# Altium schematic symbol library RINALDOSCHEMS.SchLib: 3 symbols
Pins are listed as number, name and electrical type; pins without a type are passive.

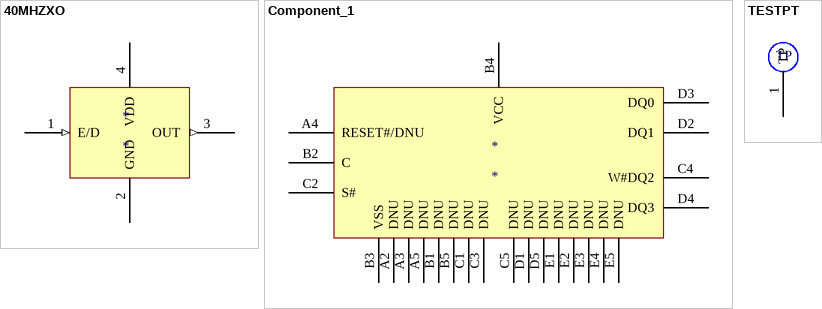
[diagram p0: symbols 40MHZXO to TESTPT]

## 40MHZXO
designator *
pins: 1 E/D (in), 2 GND (power), 3 OUT (out), 4 VDD

## Component_1
designator *
footprint BGA25C100P5X5_800X600X120N
pins: A2 DNU, A3 DNU, A4 RESET#/DNU, A5 DNU, B1 DNU, B2 C, B3 VSS (power), B4 VCC (power), B5 DNU, C1 DNU, C2 S#, C3 DNU, C4 W#DQ2, C5 DNU, D1 DNU, D2 DQ1, D3 DQ0, D4 DQ3, D5 DNU, E1 DNU, E2 DNU, E3 DNU, E4 DNU, E5 DNU

## TESTPT
designator TP, comment TEST POINT  (value not drawn)  (no BOM)
footprint TESTPOINT1 (TEST POINT PLUTO)
pins: 1 TP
